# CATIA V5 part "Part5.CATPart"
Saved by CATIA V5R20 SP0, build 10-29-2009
Part number: Part1.3
Bounding box of the stored display mesh (mm): x 0 to 104, y -13.856 to 13.856, z -12 to 12
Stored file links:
  C:\Users\hojat azimi\Desktop\New folder\Part5.CATPart
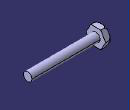
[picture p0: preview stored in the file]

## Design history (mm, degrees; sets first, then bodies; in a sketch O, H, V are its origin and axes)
Body1 (main body)
  Sketch1 on yz-plane, origin (0, 0, 0), H (0, 1, 0), V (0, 0, 1)
    line L1 (6.9282, 12) -> (-6.9282, 12)
    line L2 (-6.9282, 12) -> (-13.8564, 0)
    line L3 (-13.8564, 0) -> (-6.9282, -12)
    line L4 (-6.9282, -12) -> (6.9282, -12)
    line L5 (6.9282, -12) -> (13.8564, 0)
    line L6 (13.8564, 0) -> (6.9282, 12)
    construction line L7 (0, 0) -> (0, 12)
    circle A1 centre (0, 0) radius 10.879
    circle A2 centre (0, 0) radius 6
  MultiPad1: profile Sketch1, domains (length 8; length 104; length 8)
  Sketch2 on face of MultiPad1 from Sketch1.L6, origin (0, 10.3923, 6), H (-1, 0, 0), V (0, -0.5, 0.866)
    arc A1 centre (-4.823, 2.1052) radius 4.823 from (0, 2.1052) to (-4.823, 6.9282) ccw
    line L1 (-4.823, 6.9282) -> (3.7111, 12.6728)
    line L2 (3.7111, 12.6728) -> (0, 2.1052)
  Groove1: profile Sketch2, axis axis of face of MultiPad1 from Sketch1.A2, angle 360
